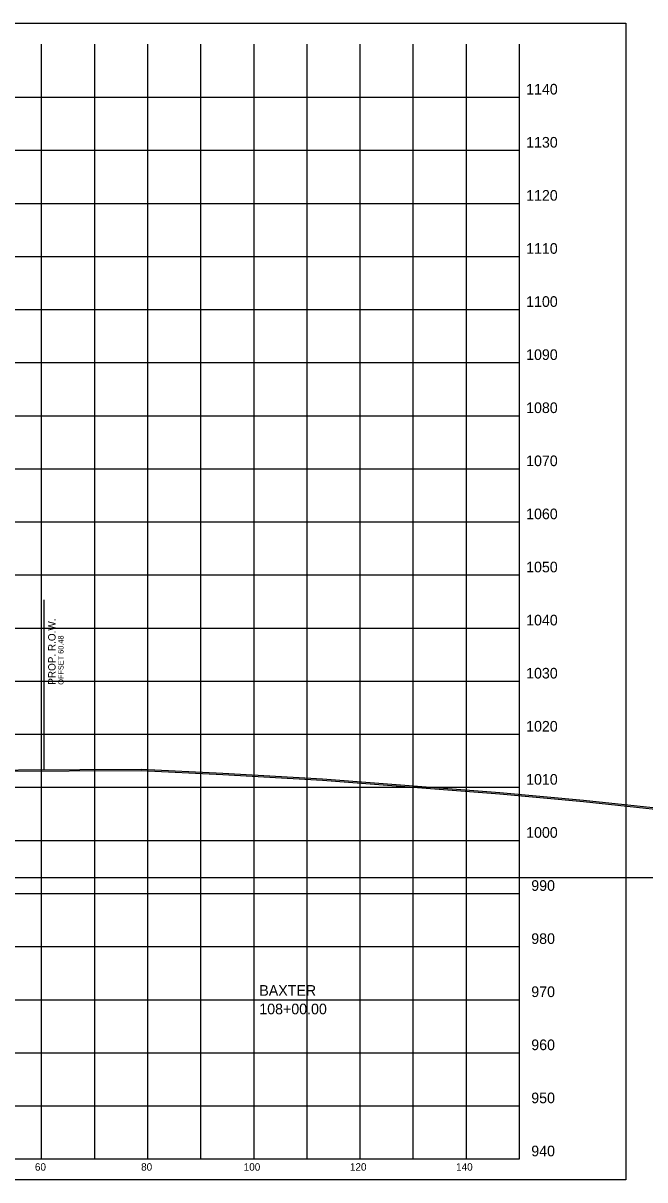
# Model space of a CAD drawing. Extents: x 5868 to 6683, y 2883 to 19120.
# Drawn here: x 6250.3 to 6367.4, y 10888.1 to 11106 of the extents above; entities that cross this region are included whole.
import ezdxf

# ---------------------------------------------------------------- set-up
doc = ezdxf.new("R2010")
doc.units = 0
for name, color, linetype in [('DESIGN - ROW - Right-of-Way and Easement Labels', 7, 'Continuous'), ('DESIGN - ROW - Right-of-Way Linework', 7, 'Continuous'), ('DESIGN - SHEET - Corner Text', 7, 'Continuous'), ('DESIGN - SHEET - Light Grid', 7, 'Continuous'), ('DESIGN - SHEET - Linework', 7, 'Continuous'), ('DESIGN - SHEET - Plot Shape', 7, 'Continuous'), ('DESIGN - TYPICAL - Warning Text', 7, 'Continuous'), ('SURVEY - GROUND - Bottom of Topsoil Layer', 7, 'Continuous'), ('SURVEY - GROUND - Top of Ground', 7, 'Continuous')]:
    doc.layers.add(name, color=color, linetype=linetype)

msp = doc.modelspace()

# ---------------------------------------------------------------- linework, layer by layer
at = {"layer": 'DESIGN - ROW - Right-of-Way Linework'}
msp.add_line((6254.26, 10965.39), (6254.26, 10997.39), dxfattribs=at)
at = {"layer": 'DESIGN - SHEET - Light Grid'}
msp.add_line((6193.78, 10945.07), (6493.78, 10945.07), dxfattribs=at)
at = {"layer": 'DESIGN - SHEET - Linework'}
for p, q in [((6253.78, 10892.07), (6253.78, 11102.07)), ((6263.78, 10892.07), (6263.78, 11102.07)), ((6273.78, 10892.07), (6273.78, 11102.07)), ((6283.78, 10892.07), (6283.78, 11102.07)), ((6293.78, 10892.07), (6293.78, 11102.07)), ((6303.78, 10892.07), (6303.78, 11102.07)), ((6313.78, 10892.07), (6313.78, 11102.07)), ((6323.78, 10892.07), (6323.78, 11102.07)), ((6333.78, 10892.07), (6333.78, 11102.07)), ((6043.78, 11092.07), (6343.78, 11092.07)), ((6043.78, 11082.07), (6343.78, 11082.07)), ((6043.78, 11072.07), (6343.78, 11072.07)), ((6043.78, 11062.07), (6343.78, 11062.07)), ((6043.78, 11052.07), (6343.78, 11052.07)), ((6043.78, 11042.07), (6343.78, 11042.07)), ((6043.78, 11032.07), (6343.78, 11032.07)), ((6043.78, 11022.07), (6343.78, 11022.07)), ((6043.78, 11012.07), (6343.78, 11012.07)), ((6043.78, 11002.07), (6343.78, 11002.07)), ((6043.78, 10992.07), (6343.78, 10992.07)), ((6043.78, 10982.07), (6343.78, 10982.07)), ((6043.78, 10972.07), (6343.78, 10972.07)), ((6043.78, 10962.07), (6343.78, 10962.07)), ((6043.78, 10952.07), (6343.78, 10952.07)), ((6043.78, 10942.07), (6343.78, 10942.07)), ((6043.78, 10932.07), (6343.78, 10932.07)), ((6043.78, 10922.07), (6343.78, 10922.07)), ((6043.78, 10912.07), (6343.78, 10912.07)), ((6043.78, 10902.07), (6343.78, 10902.07))]:
    msp.add_line(p, q, dxfattribs=at)
msp.add_lwpolyline([(6043.78, 11102.07), (6043.78, 10892.07), (6343.78, 10892.07), (6343.78, 11102.07)], dxfattribs=at)
at = {"layer": 'DESIGN - SHEET - Plot Shape'}
msp.add_lwpolyline([(6023.78, 11106.01), (6363.78, 11106.01), (6363.78, 10888.13), (6023.78, 10888.13)], close=True, dxfattribs=at)
at = {"layer": 'SURVEY - GROUND - Bottom of Topsoil Layer'}
for p, q in [((6226.18, 10964.96), (6272.55, 10965.26)), ((6272.55, 10965.26), (6287.93, 10964.49)), ((6287.93, 10964.49), (6306.71, 10963.42)), ((6306.71, 10963.42), (6340.09, 10960.86)), ((6340.09, 10960.86), (6355.81, 10959.39)), ((6355.81, 10959.39), (6384.98, 10956.3))]:
    msp.add_line(p, q, dxfattribs=at)
at = {"layer": 'SURVEY - GROUND - Top of Ground'}
msp.add_lwpolyline([(6226.18, 10965.21), (6272.55, 10965.51), (6287.93, 10964.74), (6306.71, 10963.67), (6340.09, 10961.11), (6355.81, 10959.64), (6384.98, 10956.55)], dxfattribs=at)

# ---------------------------------------------------------------- texts
at = {"layer": 'DESIGN - ROW - Right-of-Way and Easement Labels'}
for s, height, p in [('PROP. R.O.W.', 1.4, (6256.41, 10981.39)), ('OFFSET 60.48', 1, (6257.91, 10981.39))]:
    msp.add_text(s, height=height, rotation=90, dxfattribs=at).set_placement(p)
at = {"layer": 'DESIGN - SHEET - Corner Text'}
for s, height, p in [('1140', 2, (6345.03, 11092.57)), ('1130', 2, (6345.03, 11082.57)), ('1120', 2, (6345.03, 11072.57)), ('1110', 2, (6345.03, 11062.57)), ('1100', 2, (6345.03, 11052.57)), ('1090', 2, (6345.03, 11042.57)), ('1080', 2, (6345.03, 11032.57)), ('1070', 2, (6345.03, 11022.57)), ('1060', 2, (6345.03, 11012.57)), ('1050', 2, (6345.03, 11002.57)), ('1040', 2, (6345.03, 10992.57)), ('1030', 2, (6345.03, 10982.57)), ('1020', 2, (6345.03, 10972.57)), ('1010', 2, (6345.03, 10962.57)), ('1000', 2, (6345.03, 10952.57)), ('990', 2, (6346, 10942.57)), ('980', 2, (6346, 10932.57)), ('970', 2, (6346, 10922.57)), ('960', 2, (6346, 10912.57)), ('950', 2, (6346, 10902.57)), ('940', 2, (6346, 10892.57)), ('60', 1.4, (6252.52, 10889.87)), ('80', 1.4, (6272.52, 10889.87)), ('100', 1.4, (6291.84, 10889.87)), ('120', 1.4, (6311.84, 10889.87)), ('140', 1.4, (6331.84, 10889.87))]:
    msp.add_text(s, height=height, dxfattribs=at).set_placement(p)
at = {"layer": 'DESIGN - TYPICAL - Warning Text'}
for s, p in [('BAXTER', (6294.78, 10922.82)), ('108+00.00', (6294.78, 10919.32))]:
    msp.add_text(s, height=2, dxfattribs=at).set_placement(p)

doc.saveas('drawing.dxf')
